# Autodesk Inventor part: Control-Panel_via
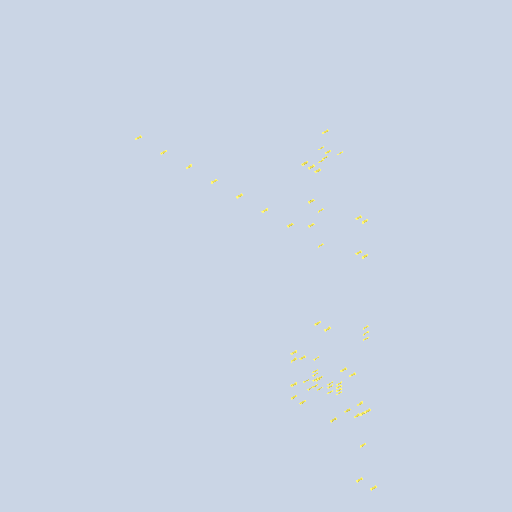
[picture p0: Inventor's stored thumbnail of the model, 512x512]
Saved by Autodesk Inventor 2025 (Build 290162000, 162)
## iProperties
Created: 2026-09
Part Number: Control-Panel_via
Material: Generic
Document SubType Name: Modeling
Designer: Leonardo
Density: 1 g/cm^3
Appearance: Default
Author: Leonardo
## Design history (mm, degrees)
feature "Base1"
feature "Base2"
feature "Base3"
feature "Base4"
feature "Base5"
feature "Base6"
feature "Base7"
feature "Base8"
feature "Base9"
feature "Base10"
feature "Base11"
feature "Base12"
feature "Base13"
feature "Base14"
feature "Base15"
feature "Base16"
feature "Base17"
feature "Base18"
feature "Base19"
feature "Base20"
feature "Base21"
feature "Base22"
feature "Base23"
feature "Base24"
feature "Base25"
feature "Base26"
feature "Base27"
feature "Base28"
feature "Base29"
feature "Base30"
feature "Base31"
feature "Base32"
feature "Base33"
feature "Base34"
feature "Base35"
feature "Base36"
feature "Base37"
feature "Base38"
feature "Base39"
feature "Base40"
feature "Base41"
feature "Base42"
feature "Base43"
feature "Base44"
feature "Base45"
feature "Base46"
feature "Base47"
feature "Base48"
feature "Base49"
feature "Base50"
feature "Base51"
feature "Base52"
feature "Base53"
feature "Base54"
feature "Base55"
feature "Base56"
feature "Base57"
feature "Base58"
feature "Base59"
feature "Base60"
feature "Base61"
feature "Base62"
feature "Base63"
body "Solid1"
body "Solid2"
body "Solid3"
body "Solid4"
body "Solid5"
body "Solid6"
body "Solid7"
body "Solid8"
body "Solid9"
body "Solid10"
body "Solid11"
body "Solid12"
body "Solid13"
body "Solid14"
body "Solid15"
body "Solid16"
body "Solid17"
body "Solid18"
body "Solid19"
body "Solid20"
body "Solid21"
body "Solid22"
body "Solid23"
body "Solid24"
body "Solid25"
body "Solid26"
body "Solid27"
body "Solid28"
body "Solid29"
body "Solid30"
body "Solid31"
body "Solid32"
body "Solid33"
body "Solid34"
body "Solid35"
body "Solid36"
body "Solid37"
body "Solid38"
body "Solid39"
body "Solid40"
body "Solid41"
body "Solid42"
body "Solid43"
body "Solid44"
body "Solid45"
body "Solid46"
body "Solid47"
body "Solid48"
body "Solid49"
body "Solid50"
body "Solid51"
body "Solid52"
body "Solid53"
body "Solid54"
body "Solid55"
body "Solid56"
body "Solid57"
body "Solid58"
body "Solid59"
body "Solid60"
body "Solid61"
body "Solid62"
body "Solid63"
